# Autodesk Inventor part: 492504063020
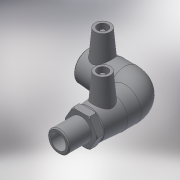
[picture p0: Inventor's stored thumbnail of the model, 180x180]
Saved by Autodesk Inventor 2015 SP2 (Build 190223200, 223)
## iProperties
Created: 2017-06
Part Number: 492504063020
Material: Generic
Description: PLASSON 90° ELBOW MALE TRANSITION 63-2"
Document SubType Name: Modeling
Designer: KIM
Mass: 508.061 g
Surface Area: 979.171 cm^2
Volume: 508.061 cm^3
Density: 1 g/cm^3
Appearance: Default
Author: KIM
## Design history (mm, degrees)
derived "492504.ipt"
feature "Solid1::492504.ipt"
tag "TaggingFeature1"
body "Solid1"
other parameters: "d2" = 82, "d4" = 43.66667, "d5" = 73.8, "d8" = 168 deg, "d10" = 22.8, "d11" = 7.6, "d29" = 59, "d30" = 15, "d31" = 72.05, "d34" = 5 deg, "d41" = 4, "d42" = 14, "d43" = 0, "d49" = 63, "d50" = 53.55, "d51" = 22.8, "d52" = 57, "d54" = 90 deg, "d57" = 63, "d58" = 57, "d59" = 0, "d61" = 90 deg, "d86" = 3, "d87" = 0, "d93" = 0.1, "d94" = 10.25, "d95" = 59.614, "d96" = 41.7298, "d97" = 48, "d98" = 41, "d99" = 82, "d100" = 36.9, "d102" = 2.52, "d106" = 0, "d_" = 63, "L_" = 172, "L_1" = 57, "D_" = 48, "A_" = 59, "d_2" = 12, "L_2" = 41, "D_1" = 82, "R_" = 59.614
